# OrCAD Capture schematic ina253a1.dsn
size A; title: INA293 40-V High-Voltage, High Bandwidth, Unidirectional, 110-V Common-Mode Current-Sense Amplifier; rev: A; note: SBOS870
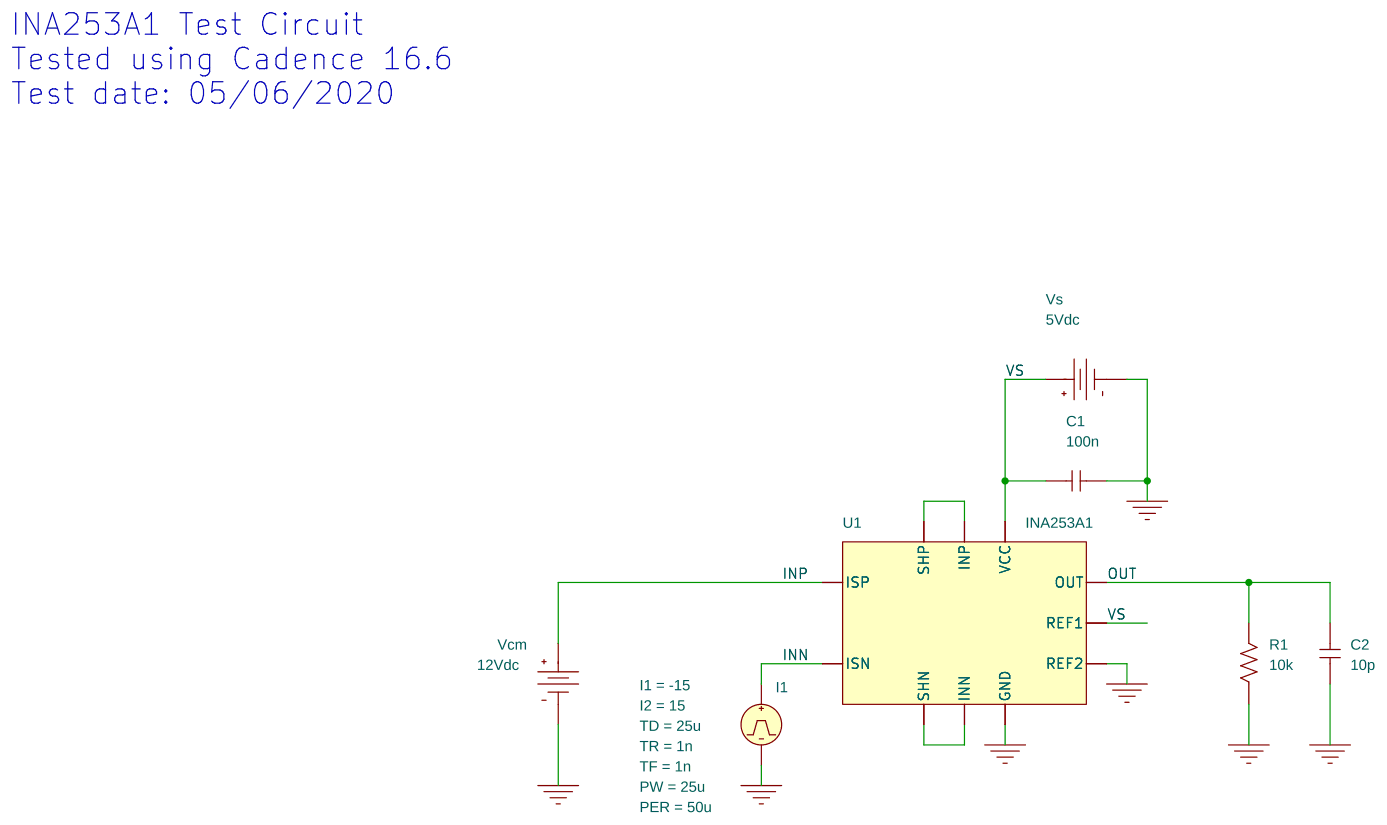
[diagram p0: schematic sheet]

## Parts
C1  100n  [RAD/CK05]
C2  10p  [RAD/CK05]
I1  IPULSE
R1  10k  [AX/RC05]
U1  INA253A1
Vcm  VDC
Vs  VDC

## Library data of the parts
C1 C2 = C
I1 = IPULSE: I1: -15; I2: 15; PER: 50u; PW: 25u; TD: 25u; TF: 1n; TR: 1n
R1 = R
U1 = INA253A1
Vcm = VDC: DC: 12Vdc
Vs = VDC: DC: 5Vdc

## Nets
0: C1.1 C2.1 I1.2(-) R1.1 U1.GND U1.REF2 Vcm.1(-) Vs.1(-)
INN: I1.1(+) U1.ISN
INP: U1.ISP Vcm.0(+)
OUT: C2.2 R1.2 U1.OUT
VS: C1.2 U1.REF1 U1.VCC Vs.0(+)
N24993: U1.INP U1.SHP
N25005: U1.INN U1.SHN

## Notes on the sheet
- INA253A1 Test Circuit
  Tested using Cadence 16.6
  Test date: 05/06/2020
